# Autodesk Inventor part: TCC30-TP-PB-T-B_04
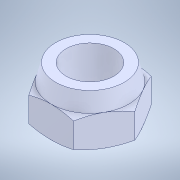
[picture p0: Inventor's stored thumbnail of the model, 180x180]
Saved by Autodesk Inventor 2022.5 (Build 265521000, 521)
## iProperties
Created: 2023-09
Part Number: TCC30-TP-PB-T-B_04
Material: 一般
Document SubType Name: Modeling
Designer: ImaoCorp
Density: 1 g/cm^3
Appearance: 既定
Author: ImaoCorp
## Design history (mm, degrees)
feature "TCC30-TP-PB-T-B_04"
node "ソリッド1"
